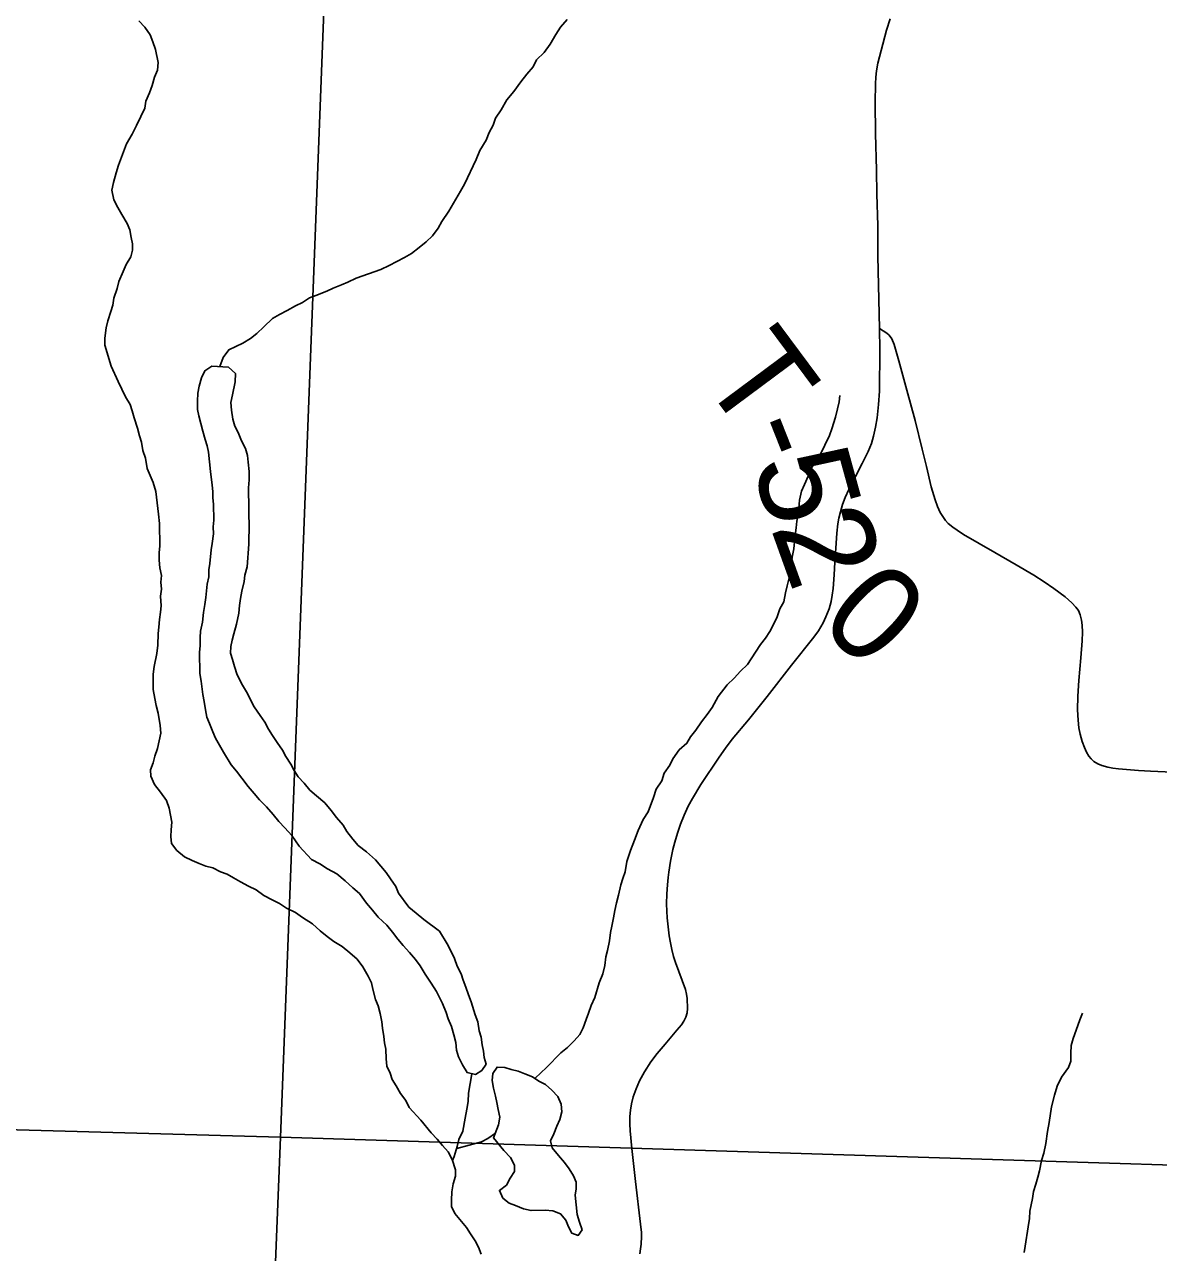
# Model space of a CAD drawing. Extents: x -3.3 to 34, y 0 to 56.8.
# Drawn here: x -2.471 to -1.801, y 32.678 to 33.404 of the extents above; entities that cross this region are included whole.
import ezdxf

# ---------------------------------------------------------------- set-up
doc = ezdxf.new("R2010")
doc.units = 0
for name, color, linetype in [('GM_X_Corporation', 7, 'Continuous'), ('GM_X_County_Road', 7, 'Continuous'), ('GM_X_Township_Road', 7, 'Continuous'), ('GM_X_Township_Road_Text', 7, 'Continuous'), ('GT_Project_Soil_Layers', 7, 'Continuous')]:
    doc.layers.add(name, color=color, linetype=linetype)

msp = doc.modelspace()

# ---------------------------------------------------------------- linework, layer by layer
at = {"layer": 'GM_X_Corporation'}
for points in [[(-3.30393, 33.67032), (-3.30393, 32.77402), (-2.31978, 32.74649), (-2.28281, 33.7097), (-3.30126, 33.74009)], [(-2.28281, 33.7097), (-1.26284, 33.67933), (-1.30168, 32.71458), (-2.31978, 32.74649)], [(-3.30393, 32.77402), (-3.30393, 31.76721), (-2.35994, 31.74572), (-2.31978, 32.74649)], [(-2.31978, 32.74649), (-1.30168, 32.71458), (-1.33537, 31.71163), (-2.35994, 31.74572)]]:
    msp.add_lwpolyline(points, close=True, dxfattribs=at)
at = {"layer": 'GM_X_County_Road'}
msp.add_lwpolyline([(-2.10742, 32.6777), (-2.1069, 32.68048), (-2.10654, 32.68335), (-2.10634, 32.68778), (-2.10641, 32.69018), (-2.1069, 32.6951), (-2.10998, 32.72035), (-2.11214, 32.73993), (-2.11308, 32.75038), (-2.1133, 32.75454), (-2.11321, 32.75882), (-2.11287, 32.76259), (-2.11232, 32.76626), (-2.11132, 32.77048), (-2.10954, 32.77526), (-2.10754, 32.77981), (-2.10454, 32.78526), (-2.10076, 32.79115), (-2.0971, 32.79614), (-2.09232, 32.80148), (-2.08543, 32.80981), (-2.08276, 32.81292), (-2.08135, 32.81514), (-2.08018, 32.81756), (-2.07943, 32.82015), (-2.0791, 32.82272), (-2.07935, 32.82856), (-2.07968, 32.83106), (-2.08043, 32.83381), (-2.08635, 32.84981), (-2.08743, 32.85348), (-2.08843, 32.85756), (-2.08926, 32.86147), (-2.08993, 32.86564), (-2.0906, 32.87089), (-2.09118, 32.87631), (-2.09143, 32.88014), (-2.09152, 32.88456), (-2.09135, 32.89047), (-2.09101, 32.89572), (-2.0906, 32.90014), (-2.09018, 32.90331), (-2.08918, 32.90972), (-2.08793, 32.91664), (-2.08674, 32.92096), (-2.08517, 32.92637), (-2.08332, 32.93169), (-2.08121, 32.93693), (-2.07871, 32.94225), (-2.07624, 32.94691), (-2.07124, 32.95511), (-2.06052, 32.9712), (-2.05667, 32.97662), (-2.05271, 32.98181), (-2.04314, 32.99326), (-2.03199, 33.00706), (-2.01765, 33.02569), (-2.00453, 33.04216), (-2.00166, 33.04601), (-1.99892, 33.05069), (-1.99726, 33.05418), (-1.99545, 33.05899), (-1.99426, 33.06326), (-1.99353, 33.06697), (-1.99304, 33.07092), (-1.99235, 33.07913), (-1.99194, 33.08647), (-1.99152, 33.0948), (-1.99086, 33.1038), (-1.99027, 33.10913), (-1.9896, 33.11255), (-1.98877, 33.11638), (-1.98752, 33.12072), (-1.98593, 33.12488), (-1.98368, 33.12954), (-1.97586, 33.14496), (-1.97227, 33.15204), (-1.97044, 33.1568), (-1.9691, 33.16096), (-1.96791, 33.16634), (-1.96704, 33.17182), (-1.96624, 33.17984), (-1.96568, 33.18763), (-1.96545, 33.21219), (-1.96568, 33.22467), (-1.96651, 33.26746), (-1.96668, 33.28563), (-1.96711, 33.3042), (-1.96744, 33.31837), (-1.96794, 33.33995), (-1.96819, 33.35829), (-1.96802, 33.36937), (-1.96777, 33.37329), (-1.96744, 33.37712), (-1.96652, 33.38154), (-1.96469, 33.38904), (-1.96144, 33.40103), (-1.95935, 33.40787)], dxfattribs=at)
at = {"layer": 'GM_X_Township_Road'}
msp.add_lwpolyline([(-1.78809, 32.96217), (-1.80526, 32.96298), (-1.81242, 32.96331), (-1.82425, 32.9643), (-1.82762, 32.96471), (-1.83067, 32.96537), (-1.83411, 32.96635), (-1.83658, 32.96734), (-1.8388, 32.96873), (-1.84045, 32.97021), (-1.84184, 32.97194), (-1.84316, 32.97423), (-1.84444, 32.97689), (-1.84579, 32.98056), (-1.847, 32.98496), (-1.84774, 32.98866), (-1.84819, 32.99317), (-1.84851, 32.99931), (-1.84842, 33.00737), (-1.84775, 33.01652), (-1.84664, 33.02991), (-1.84579, 33.04001), (-1.84562, 33.04518), (-1.84579, 33.04921), (-1.84612, 33.05225), (-1.84686, 33.05537), (-1.84801, 33.05801), (-1.84949, 33.05998), (-1.85195, 33.06252), (-1.8559, 33.06606), (-1.86247, 33.07107), (-1.86815, 33.07494), (-1.8744, 33.07888), (-1.88476, 33.08505), (-1.89749, 33.0922), (-1.91591, 33.10289), (-1.91977, 33.10544), (-1.92224, 33.10716), (-1.92495, 33.10946), (-1.92651, 33.11119), (-1.92783, 33.113), (-1.92964, 33.11596), (-1.93128, 33.11941), (-1.93276, 33.12336), (-1.93498, 33.13109), (-1.93785, 33.14304), (-1.94032, 33.15336), (-1.94459, 33.17038), (-1.94952, 33.18829), (-1.95426, 33.20553), (-1.95695, 33.21529), (-1.95838, 33.21862), (-1.95981, 33.22069), (-1.96123, 33.22189), (-1.96568, 33.22467)], dxfattribs=at)
at = {"layer": 'GT_Project_Soil_Layers'}
for points in [[(-2.40356, 33.4066), (-2.40009, 33.40285), (-2.397, 33.39833), (-2.39542, 33.39418), (-2.39384, 33.38964), (-2.39222, 33.38207), (-2.39254, 33.3775), (-2.39438, 33.3733), (-2.39583, 33.36834), (-2.39728, 33.36414), (-2.39949, 33.35918), (-2.40019, 33.35499), (-2.4024, 33.35002), (-2.40498, 33.34467), (-2.40756, 33.33969), (-2.4109, 33.33395), (-2.41382, 33.32593), (-2.41566, 33.32135), (-2.41711, 33.31677), (-2.41855, 33.31106), (-2.41962, 33.30648), (-2.41841, 33.3008), (-2.41607, 33.29628), (-2.41374, 33.29213), (-2.41063, 33.28685), (-2.40906, 33.28308)], [(-2.15026, 33.40741), (-2.15437, 33.4028), (-2.15697, 33.39858), (-2.1603, 33.39284), (-2.16402, 33.38785), (-2.16852, 33.38361), (-2.17036, 33.37941), (-2.17409, 33.37518), (-2.17782, 33.37057), (-2.18191, 33.36482), (-2.18601, 33.35982), (-2.18935, 33.35408), (-2.19269, 33.3491), (-2.19415, 33.3449), (-2.19637, 33.34069), (-2.1982, 33.33611), (-2.20191, 33.32998), (-2.20411, 33.32463), (-2.21112, 33.3101), (-2.21333, 33.30589), (-2.22037, 33.29402), (-2.22446, 33.28789), (-2.22668, 33.28406), (-2.23003, 33.27946), (-2.23378, 33.27599), (-2.2379, 33.27251), (-2.2424, 33.26903), (-2.24654, 33.26669), (-2.25558, 33.26201), (-2.26047, 33.25967), (-2.27519, 33.25453), (-2.28009, 33.25218), (-2.28386, 33.25061), (-2.28876, 33.24864), (-2.29253, 33.24669), (-2.29894, 33.24432), (-2.30271, 33.24275), (-2.30684, 33.24003), (-2.31099, 33.23808), (-2.31588, 33.23535), (-2.3204, 33.23301), (-2.32454, 33.23068), (-2.32978, 33.22567), (-2.3339, 33.22181), (-2.33765, 33.21872), (-2.34216, 33.216), (-2.35045, 33.21209), (-2.3538, 33.20748), (-2.35579, 33.20215)], [(-2.40906, 33.28308), (-2.40824, 33.27853), (-2.40743, 33.27474), (-2.40738, 33.27094), (-2.40846, 33.26713), (-2.41105, 33.26254), (-2.41289, 33.25833), (-2.41547, 33.2526), (-2.41655, 33.24841), (-2.41836, 33.24268), (-2.41906, 33.2385), (-2.42015, 33.23468), (-2.42197, 33.22934), (-2.42305, 33.22515), (-2.42373, 33.21906), (-2.42367, 33.21488), (-2.42009, 33.20239), (-2.41579, 33.19334), (-2.41149, 33.18428), (-2.40878, 33.17976), (-2.40759, 33.17597), (-2.40639, 33.17181), (-2.40441, 33.16576), (-2.40321, 33.16122), (-2.40202, 33.15744), (-2.4012, 33.15251), (-2.39961, 33.14797), (-2.39877, 33.14191), (-2.39525, 33.1336), (-2.39366, 33.1283), (-2.39196, 33.11503), (-2.3915, 33.10934), (-2.39131, 33.09604), (-2.39164, 33.09224), (-2.39158, 33.08768), (-2.39114, 33.08313), (-2.39032, 33.07858), (-2.39064, 33.07478), (-2.39021, 33.0706), (-2.39091, 33.06642), (-2.39045, 33.06072), (-2.39077, 33.05692), (-2.39148, 33.05273), (-2.39179, 33.04817), (-2.39212, 33.04436), (-2.3924, 33.03752), (-2.39309, 33.03257), (-2.3945, 33.02496), (-2.3952, 33.02039), (-2.39507, 33.01127), (-2.39424, 33.00596), (-2.39343, 33.0018), (-2.39223, 32.99725), (-2.39099, 32.99005), (-2.39055, 32.9855), (-2.3927, 32.97635), (-2.39415, 32.97177), (-2.39524, 32.96796), (-2.39669, 32.96376), (-2.39664, 32.95996), (-2.3943, 32.95506), (-2.39082, 32.95054), (-2.38734, 32.94565), (-2.38576, 32.94112), (-2.38413, 32.93278), (-2.38445, 32.92822), (-2.38477, 32.92442), (-2.38434, 32.92024), (-2.38125, 32.9161), (-2.37664, 32.91237), (-2.37206, 32.91015), (-2.36787, 32.90831), (-2.36406, 32.90684), (-2.35987, 32.90576), (-2.35529, 32.90355), (-2.35148, 32.90208), (-2.34765, 32.89985), (-2.34345, 32.89763), (-2.33887, 32.89503), (-2.33429, 32.89282), (-2.32969, 32.88946), (-2.32472, 32.88687), (-2.32052, 32.88465), (-2.31631, 32.88205), (-2.31097, 32.87946), (-2.30676, 32.87648), (-2.30102, 32.87276), (-2.29641, 32.86865), (-2.29219, 32.86529), (-2.28836, 32.8623), (-2.28339, 32.85933), (-2.27879, 32.85559), (-2.27457, 32.85185), (-2.27109, 32.84734), (-2.26798, 32.84169), (-2.26603, 32.83791)], [(-2.23735, 32.84781), (-2.24006, 32.85157), (-2.24352, 32.8557), (-2.24738, 32.85983), (-2.25046, 32.86358), (-2.25355, 32.86772), (-2.25702, 32.87185), (-2.26202, 32.87672), (-2.26549, 32.88085), (-2.26896, 32.88498), (-2.27321, 32.89062), (-2.27704, 32.89399), (-2.28165, 32.8981), (-2.28664, 32.90221), (-2.29199, 32.90518), (-2.29658, 32.90816), (-2.30154, 32.91075), (-2.30886, 32.91862), (-2.31312, 32.92502), (-2.31735, 32.92952), (-2.32081, 32.93327), (-2.32428, 32.9374), (-2.32814, 32.94191), (-2.33237, 32.94603), (-2.33545, 32.94979), (-2.33892, 32.95392), (-2.34278, 32.95881), (-2.34587, 32.96294), (-2.34896, 32.9667), (-2.35361, 32.97423), (-2.35827, 32.98253), (-2.35984, 32.9863), (-2.36181, 32.99121), (-2.36338, 32.99499), (-2.36419, 32.99916), (-2.36502, 33.00409), (-2.36584, 33.00826), (-2.3667, 33.01622), (-2.36752, 33.02077), (-2.3677, 33.0333), (-2.36737, 33.03711), (-2.36744, 33.04204), (-2.36711, 33.04585), (-2.36605, 33.05118), (-2.36537, 33.05689), (-2.36467, 33.06146), (-2.36397, 33.06565), (-2.36332, 33.07363), (-2.36225, 33.07783), (-2.3623, 33.082), (-2.3616, 33.08581), (-2.36095, 33.0938), (-2.36024, 33.09761), (-2.35956, 33.10332), (-2.35962, 33.1075), (-2.3593, 33.1113), (-2.35943, 33.12079), (-2.35986, 33.12459), (-2.35991, 33.12838), (-2.36034, 33.13218), (-2.36121, 33.14014), (-2.3625, 33.15152), (-2.36331, 33.15531), (-2.3645, 33.15909), (-2.36571, 33.16401), (-2.36811, 33.1731), (-2.36892, 33.17689), (-2.36899, 33.18182), (-2.36867, 33.18639), (-2.36797, 33.19057), (-2.36652, 33.19553), (-2.36468, 33.19974), (-2.36055, 33.20245), (-2.35068, 33.20183)], [(-2.35068, 33.20183), (-2.34646, 33.19809), (-2.34677, 33.19314), (-2.34819, 33.18553), (-2.34926, 33.18096), (-2.34882, 33.1764), (-2.34799, 33.1711), (-2.34679, 33.16693), (-2.34484, 33.16316), (-2.34288, 33.15825), (-2.34054, 33.15372), (-2.33935, 33.14956), (-2.33891, 33.14577), (-2.33846, 33.14008), (-2.33839, 33.13514), (-2.3387, 33.13058), (-2.33836, 33.10551), (-2.33867, 33.10094), (-2.33862, 33.09715), (-2.33958, 33.08384), (-2.34102, 33.07888), (-2.34135, 33.07507), (-2.34279, 33.06936), (-2.34349, 33.06517), (-2.34419, 33.06098), (-2.34451, 33.05642), (-2.34593, 33.04994), (-2.34737, 33.04422), (-2.34846, 33.04041), (-2.34916, 33.0366), (-2.34949, 33.03279), (-2.3483, 33.02901), (-2.34711, 33.02485), (-2.34552, 33.01993), (-2.3424, 33.0139), (-2.3393, 33.009), (-2.33735, 33.00485), (-2.3354, 33.00108), (-2.33192, 32.99581), (-2.32921, 32.99204), (-2.32688, 32.9879), (-2.32455, 32.98413), (-2.32184, 32.97999), (-2.31874, 32.97547), (-2.31679, 32.9717), (-2.3137, 32.96718), (-2.31175, 32.96341), (-2.30942, 32.95964), (-2.30596, 32.95589), (-2.30249, 32.95176), (-2.29865, 32.9484), (-2.29366, 32.94429), (-2.28981, 32.93978), (-2.28672, 32.93564), (-2.28287, 32.93114), (-2.28054, 32.92737), (-2.27706, 32.92286), (-2.27398, 32.9191), (-2.269, 32.91537), (-2.26362, 32.91051), (-2.25745, 32.903), (-2.25474, 32.89924), (-2.25165, 32.89472), (-2.25008, 32.89094), (-2.2439, 32.88267), (-2.23968, 32.87893), (-2.23507, 32.87519), (-2.22588, 32.86848), (-2.22123, 32.86095), (-2.21889, 32.85642), (-2.21694, 32.85227), (-2.21536, 32.84773), (-2.21302, 32.84321), (-2.21183, 32.83942), (-2.21026, 32.83527), (-2.20867, 32.83073), (-2.2071, 32.82657), (-2.20472, 32.81901), (-2.20315, 32.81485), (-2.20232, 32.80954), (-2.20113, 32.80576), (-2.20068, 32.80121), (-2.19987, 32.79742), (-2.19944, 32.79363), (-2.19825, 32.78984), (-2.20085, 32.78601), (-2.20461, 32.78368), (-2.20956, 32.78475), (-2.21227, 32.78927), (-2.21462, 32.79417), (-2.21581, 32.79796), (-2.21625, 32.80251), (-2.21745, 32.80705), (-2.21865, 32.81198), (-2.22061, 32.81651), (-2.2218, 32.82029), (-2.22415, 32.82557), (-2.22766, 32.83275), (-2.23076, 32.83764), (-2.23425, 32.84291), (-2.23735, 32.84781)], [(-1.98908, 33.18515), (-1.98941, 33.18135), (-1.99049, 33.17715), (-1.99156, 33.1722), (-1.99374, 33.16533), (-1.9952, 33.16152), (-2.00074, 33.15004), (-2.00668, 33.14122), (-2.00777, 33.13741), (-2.00997, 33.13244), (-2.01181, 33.12862), (-2.01288, 33.12328), (-2.01354, 33.11606), (-2.0146, 33.11073), (-2.01493, 33.10692), (-2.0156, 33.10084), (-2.01627, 33.09437), (-2.01734, 33.08942), (-2.01767, 33.08561), (-2.01838, 33.08181), (-2.01907, 33.07724), (-2.02014, 33.07266), (-2.02122, 33.06847), (-2.02229, 33.06314), (-2.02451, 33.05893), (-2.02633, 33.05358), (-2.03039, 33.04555), (-2.03299, 33.04172), (-2.03597, 33.03788), (-2.03894, 33.03328), (-2.04377, 33.02599), (-2.04789, 33.02214), (-2.05162, 33.01791), (-2.05574, 33.01405), (-2.06095, 33.00714), (-2.06465, 33.00063), (-2.06763, 32.99641), (-2.07098, 32.99219), (-2.07433, 32.9872), (-2.07731, 32.98336), (-2.07953, 32.97953), (-2.08403, 32.97567), (-2.08775, 32.9703), (-2.08959, 32.96648), (-2.09294, 32.96187), (-2.09439, 32.95729), (-2.09774, 32.95231), (-2.09918, 32.94735), (-2.10248, 32.93895), (-2.10545, 32.93435), (-2.10839, 32.92785), (-2.11059, 32.92212), (-2.11278, 32.91601), (-2.11497, 32.90952), (-2.11602, 32.90343), (-2.11749, 32.89961), (-2.11857, 32.8958), (-2.12, 32.8897), (-2.12108, 32.88513), (-2.12215, 32.88055), (-2.12285, 32.87636), (-2.12392, 32.87141), (-2.12463, 32.8676), (-2.12532, 32.86265), (-2.12638, 32.85694), (-2.12746, 32.85313), (-2.12815, 32.84818), (-2.12922, 32.84323), (-2.13142, 32.83788), (-2.13395, 32.8291), (-2.13617, 32.82451), (-2.13762, 32.81994), (-2.13908, 32.81612), (-2.14091, 32.81115), (-2.14275, 32.80733), (-2.14611, 32.80348), (-2.15023, 32.79963), (-2.15398, 32.79653), (-2.16258, 32.78768), (-2.16917, 32.78157)], [(-2.26603, 32.83791), (-2.26522, 32.83413), (-2.26362, 32.82807), (-2.26205, 32.82429), (-2.26085, 32.81975), (-2.26002, 32.81482), (-2.25959, 32.81103), (-2.25877, 32.8061), (-2.25834, 32.80231), (-2.25752, 32.79852), (-2.25745, 32.79282), (-2.25701, 32.78865), (-2.25506, 32.7845), (-2.25387, 32.78071), (-2.25154, 32.77695), (-2.24882, 32.77243), (-2.24573, 32.76829), (-2.24378, 32.76414), (-2.23685, 32.75664), (-2.23068, 32.74912), (-2.22722, 32.74538), (-2.22413, 32.74162), (-2.22067, 32.73787), (-2.21833, 32.73334), (-2.21635, 32.72729), (-2.2163, 32.72349), (-2.21775, 32.71891), (-2.21844, 32.71434), (-2.21876, 32.7094), (-2.2187, 32.7056), (-2.21675, 32.70145), (-2.20981, 32.69319), (-2.20748, 32.68942), (-2.20477, 32.68528), (-2.20282, 32.68151), (-2.20125, 32.67735)], [(-1.84564, 32.81981), (-1.84711, 32.81599), (-1.8493, 32.80988), (-1.85113, 32.80491), (-1.8522, 32.80072), (-1.85252, 32.79616), (-1.85246, 32.7916), (-1.85392, 32.78778), (-1.85802, 32.78203), (-1.8606, 32.77667), (-1.86204, 32.77133), (-1.86384, 32.76447), (-1.86523, 32.75533), (-1.86629, 32.75), (-1.86733, 32.74277), (-1.86839, 32.73706), (-1.86985, 32.73286), (-1.8709, 32.72677), (-1.87199, 32.72295), (-1.87307, 32.71876), (-1.87453, 32.71456), (-1.87523, 32.71037), (-1.87664, 32.70275), (-1.87696, 32.69857), (-1.87765, 32.69362), (-1.87939, 32.6822), (-1.8801, 32.67839)], [(-2.14154, 32.69186), (-2.14312, 32.69639), (-2.14432, 32.70093), (-2.14561, 32.71232), (-2.14491, 32.71612), (-2.14496, 32.71992), (-2.14653, 32.7237), (-2.14924, 32.72784), (-2.15195, 32.7316), (-2.15542, 32.73573), (-2.15927, 32.74024), (-2.16009, 32.74441), (-2.15825, 32.74861), (-2.15642, 32.75319), (-2.15457, 32.75702), (-2.1535, 32.76159), (-2.15394, 32.76614), (-2.1559, 32.77067), (-2.15936, 32.77443), (-2.1632, 32.77779), (-2.16702, 32.77964), (-2.17085, 32.78225), (-2.17542, 32.78408), (-2.17923, 32.78555), (-2.18342, 32.78663), (-2.18723, 32.78772), (-2.19178, 32.78803), (-2.19438, 32.7842), (-2.1947, 32.78002), (-2.19388, 32.77547), (-2.19268, 32.77092), (-2.19187, 32.76714), (-2.19106, 32.76297), (-2.19024, 32.75842), (-2.19093, 32.75385), (-2.19386, 32.74622), (-2.18769, 32.7387), (-2.18384, 32.73458), (-2.1815, 32.73005), (-2.18145, 32.72625), (-2.18405, 32.72242), (-2.18627, 32.71821), (-2.1904, 32.71511), (-2.18844, 32.71058), (-2.1846, 32.7076), (-2.18079, 32.70613), (-2.17622, 32.70429), (-2.17165, 32.70322), (-2.16331, 32.70333), (-2.15876, 32.70301), (-2.15418, 32.70118), (-2.15109, 32.69742), (-2.14953, 32.69364), (-2.14758, 32.68987), (-2.14382, 32.68849), (-2.14154, 32.69186)], [(-2.2067, 32.78413), (-2.20863, 32.7726), (-2.20894, 32.76766), (-2.20964, 32.76309), (-2.2107, 32.75776), (-2.21211, 32.75014), (-2.21432, 32.74517), (-2.2154, 32.74098), (-2.21722, 32.73525), (-2.21817, 32.73286)], [(-2.21566, 32.73996), (-2.20103, 32.74384), (-2.19727, 32.74579), (-2.19276, 32.74889)]]:
    msp.add_lwpolyline(points, dxfattribs=at)

# ---------------------------------------------------------------- texts
at = {"layer": 'GM_X_Township_Road_Text'}
for s, rotation, p in [('T', 306.62733, (-2.07245, 33.19614)), ('-', 291.5492, (-2.04901, 33.16548)), ('5', 285.42217, (-2.04095, 33.1453)), ('2', 289.78138, (-2.03022, 33.10707)), ('0', 316.18812, (-2.00297, 33.0504))]:
    msp.add_text(s, height=0.05682, rotation=rotation, dxfattribs=at).set_placement(p)

doc.saveas('drawing.dxf')
